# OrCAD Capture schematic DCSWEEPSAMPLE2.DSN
size A
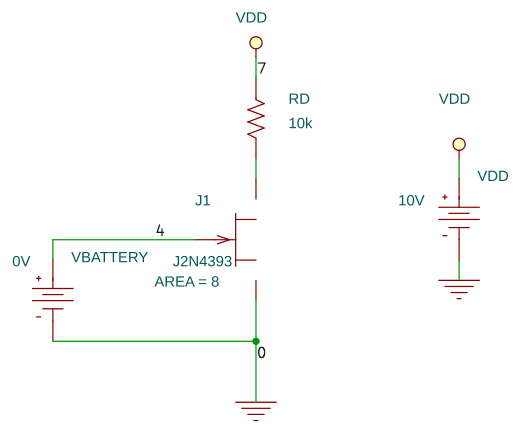
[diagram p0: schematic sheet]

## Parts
J1  J2N4393  [TO18]
RD  10k  [AX/RC05]
VBATTERY  VDC
VDD  VDC

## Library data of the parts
J1 = J2N4393: AREA: 8
RD = R
VBATTERY = VDC: DC: 0V
VDD = VDC: DC: 10V

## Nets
VDD: RD.1 VDD.0(+)
0: J1.1(s) VBATTERY.1(-) VDD.1(-)
4: J1.3(g) VBATTERY.0(+)
N00926: J1.2(d) RD.2
